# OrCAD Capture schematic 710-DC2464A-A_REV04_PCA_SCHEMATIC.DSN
size C; note: HOT SWAPPABLE SUPER CAPACITOR CHARGER AND BACKUP CONTROLLER
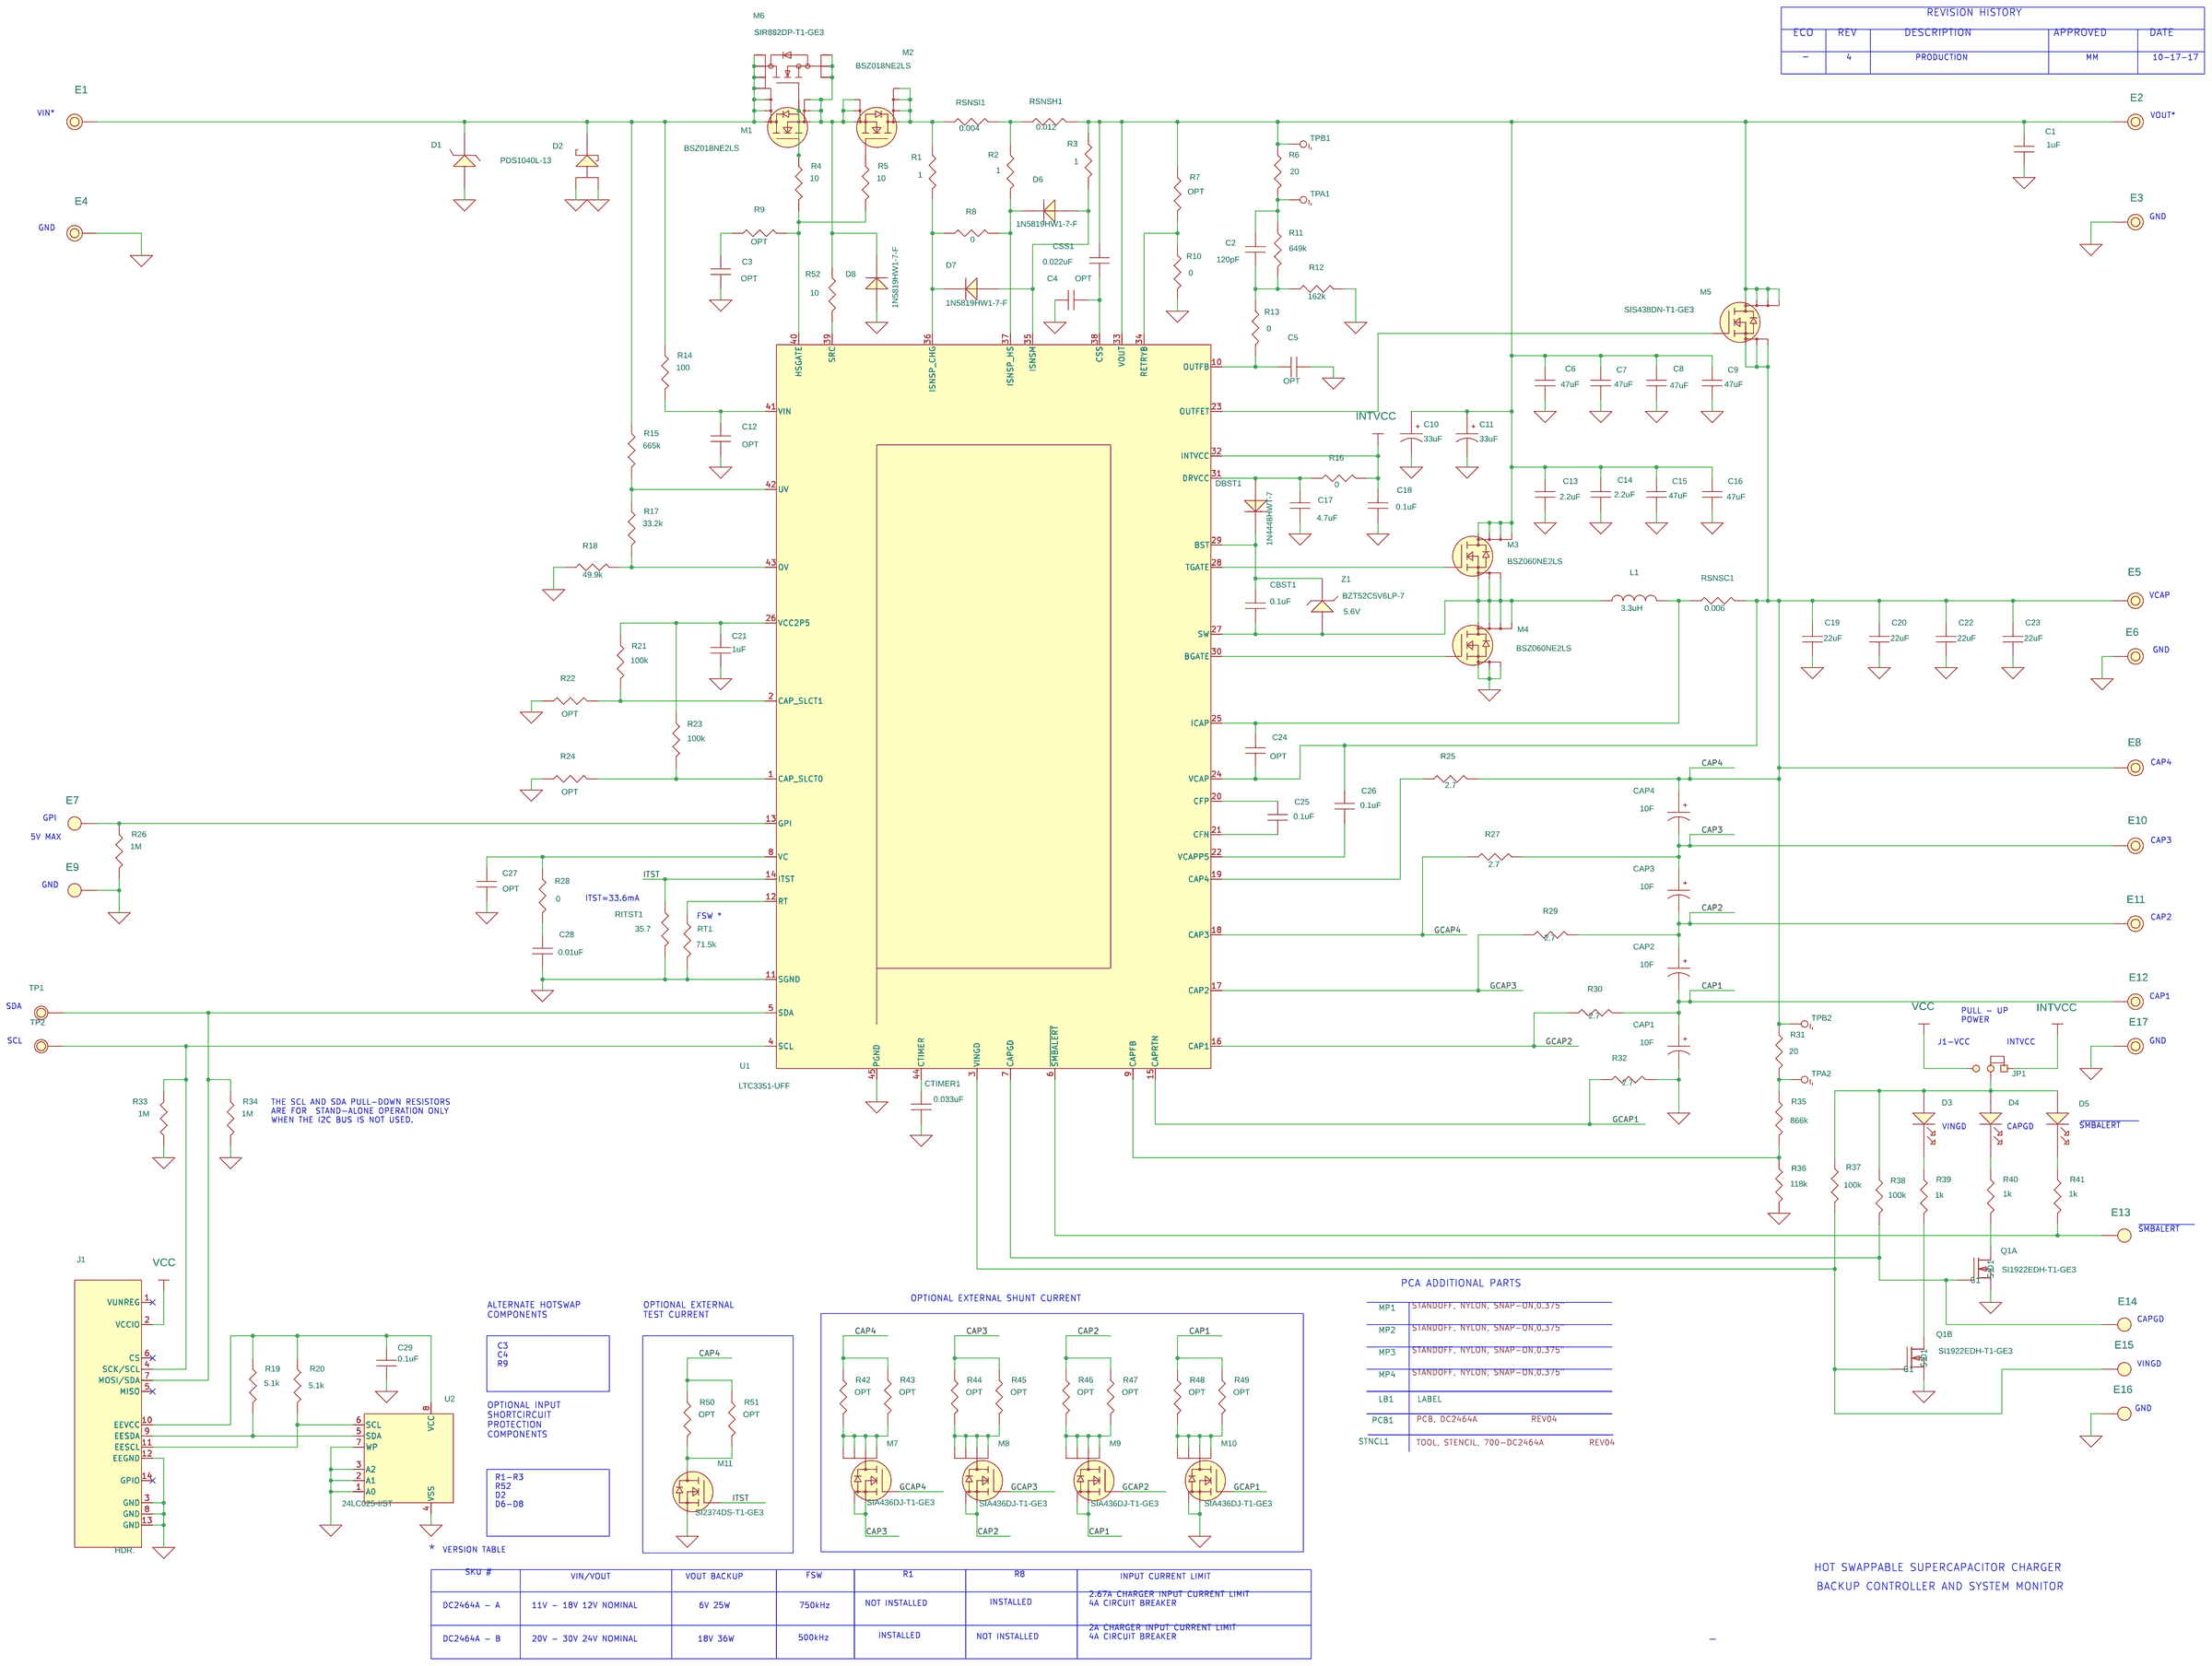
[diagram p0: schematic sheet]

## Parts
C1  1uF  [CC0603M]
C2  120pF  [CC0402M]
C3  OPT  [CC0603M]
C4  OPT  [CC0603M]
C5  OPT  [CC0402M]
C6  47uF  [CC1206M]
C7  47uF  [CC1206M]
C8  47uF  [CC1206M]
C9  47uF  [CC1206M]
C10  33uF  [PCAP_EEHZ_D8-M]
C11  33uF  [PCAP_EEHZ_D8-M]
C12  OPT  [CC0402M]
C13  2.2uF  [CC0402M]
C14  2.2uF  [CC0402M]
C15  47uF  [CC1206M]
C16  47uF  [CC1206M]
C17  4.7uF  [CC0603M]
C18  0.1uF  [CC0402M]
C19  22uF  [CC0805M]
C20  22uF  [CC0805M]
C21  1uF  [CC0402M]
C22  22uF  [CC0805M]
C23  22uF  [CC0805M]
C24  OPT  [CC0402M]
C25  0.1uF  [CC0402M]
C26  0.1uF  [CC0402M]
C27  OPT  [CC0402M]
C28  0.01uF  [CC0402M]
C29  0.1uF  [CC0402M]
CAP1  10F  [CAP-ESHSR-0010-0050C0-002R7]
CAP2  10F  [CAP-ESHSR-0010-0050C0-002R7]
CAP3  10F  [CAP-ESHSR-0010-0050C0-002R7]
CAP4  10F  [CAP-ESHSR-0010-0050C0-002R7]
CBST1  0.1uF  [CC0402M]
CSS1  0.022uF  [CC0603M]
CTIMER1  0.033uF  [CC0402M]
D1  SMBJ18A  [FAIRCHILD-DO-214AA]
D2  PDS1040L-13  [POWERDI5]
D3  GREEN  [LUMEX-SML-LX0603GW-TR]
D4  GREEN  [LUMEX-SML-LX0603GW-TR]
D5  SUPER RED  [LUMEX-SML-LX0603SRW-TR]
D6  1N5819HW1-7-F  [SOD-123F-N]
D7  1N5819HW1-7-F  [SOD-123F-N]
D8  1N5819HW1-7-F  [SOD-123F-N]
DBST1  1N4448HWT-7  [SOD-523N]
E1  TEST POINT  [MILLMAX2501]
E2  TEST POINT  [MILLMAX2501]
E3  TEST POINT  [MILLMAX2501]
E4  TEST POINT  [MILLMAX2501]
E5  TEST POINT  [MILLMAX2501]
E6  TEST POINT  [MILLMAX2501]
E7  TEST POINT  [MILLMAX2308]
E8  TEST POINT  [MILLMAX2501]
E9  TEST POINT  [MILLMAX2308]
E10  TEST POINT  [MILLMAX2501]
E11  TEST POINT  [MILLMAX2501]
E12  TEST POINT  [MILLMAX2501]
E13  TEST POINT  [MILLMAX2308]
E14  TEST POINT  [MILLMAX2308]
E15  TEST POINT  [MILLMAX2308]
E16  TEST POINT  [MILLMAX2308]
E17  TEST POINT  [MILLMAX2501]
J1  HDR.  [HD2X7-079-MOLEX]
JP1  HDR  [HD1X3-079]
L1  3.3uH  [IND-XAL7030]
LB1  LABEL  [895-0154_REV01]
M1  BSZ018NE2LS  [PG-TSDSON-8]
M2  BSZ018NE2LS  [PG-TSDSON-8]
M3  BSZ060NE2LS  [PG-TSDSON-8]
M4  BSZ060NE2LS  [PG-TSDSON-8]
M5  SIS438DN-T1-GE3  [POWERPAK1212-8S]
M6  SIR882DP-T1-GE3  [POWERPAKSO-8]
M7  SIA436DJ-T1-GE3  [POWERPAK-SC-70-6L-SINGLE]
M8  SIA436DJ-T1-GE3  [POWERPAK-SC-70-6L-SINGLE]
M9  SIA436DJ-T1-GE3  [POWERPAK-SC-70-6L-SINGLE]
M10  SIA436DJ-T1-GE3  [POWERPAK-SC-70-6L-SINGLE]
M11  SI2374DS-T1-GE3  [SOT23-3N]
MP1  STANDOFF, NYLON, SNAP-ON  [KEYSTONE_8829-8834]
MP2  STANDOFF, NYLON, SNAP-ON  [KEYSTONE_8829-8834]
MP3  STANDOFF, NYLON, SNAP-ON  [KEYSTONE_8829-8834]
MP4  STANDOFF, NYLON, SNAP-ON  [KEYSTONE_8829-8834]
PCB1  PCB, DC2464A
Q1  SI1922EDH-T1-GE3  [SC-70-6N-VISHAY]  (sections A,B)
R1  1  [CR0402M]
R2  1  [CR0402M]
R3  1  [CR0402M]
R4  10  [CR0402M]
R5  10  [CR0402M]
R6  20  [CR0402M]
R7  OPT  [CR0402M]
R8  0  [CR0402M]
R9  OPT  [CR0402M]
R10  0  [CR0402M]
R11  649k  [CR0402M]
R12  162k  [CR0402M]
R13  0  [CR0402M]
R14  100  [CR0402M]
R15  665k  [CR0402M]
R16  0  [CR0402M]
R17  33.2k  [CR0402M]
R18  49.9k  [CR0402M]
R19  5.1k  [CR0402M]
R20  5.1k  [CR0402M]
R21  100k  [CR0402M]
R22  OPT  [CR0402M]
R23  100k  [CR0402M]
R24  OPT  [CR0402M]
R25  2.7  [CR0805M]
R26  1M  [CR0402M]
R27  2.7  [CR0805M]
R28  0  [CR0402M]
R29  2.7  [CR0805M]
R30  2.7  [CR0805M]
R31  20  [CR0402M]
R32  2.7  [CR0805M]
R33  1M  [CR0402M]
R34  1M  [CR0402M]
R35  866k  [CR0402M]
R36  118k  [CR0402M]
R37  100k  [CR0402M]
R38  100k  [CR0402M]
R39  1k  [CR0402M]
R40  1k  [CR0402M]
R41  1k  [CR0402M]
R42  OPT  [CR2512N]
R43  OPT  [CR2512N]
R44  OPT  [CR2512N]
R45  OPT  [CR2512N]
R46  OPT  [CR2512N]
R47  OPT  [CR2512N]
R48  OPT  [CR2512N]
R49  OPT  [CR2512N]
R50  OPT  [CR2512N]
R51  OPT  [CR2512N]
R52  10  [CR0402M]
RITST1  35.7  [CR0402M]
RSNSC1  0.006  [1206-PRL1632]
RSNSH1  0.012  [1206-PRL1632]
RSNSI1  0.004  [1206-PRL1632]
RT1  71.5k  [CR0402M]
STNCL1  TOOL, STENCIL, 700-DC2464A
TP1  TEST PAD  [PADSTYLE2]
TP2  TEST PAD  [PADSTYLE2]
TPA1  COPPER FEATURE PAD  [PADSTYLE1]
TPA2  COPPER FEATURE PAD  [PADSTYLE1]
TPB1  COPPER FEATURE PAD  [PADSTYLE1]
TPB2  COPPER FEATURE PAD  [PADSTYLE1]
U1  LTC3351-UFF  [LTC-UFF-44-1762]
U2  24LC025-I/ST  [MICROCHIP-TSSOP-8]
XJP1  SHUNT
Z1  BZT52C5V6LP-7  [X1-DFN1006-2]

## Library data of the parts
C1 = CAP: CAP.,1uF,X5R,50V,10%,0603,AEC-Q200; CLASS: DISCRETE; Dielectric Type: X5R; FPLIST: CC0603N,CC0603L,CC0603M; Manufacturer: TDK; Manufacturer PN: CGA3E3X5R1H105K080AB; PART_NUMBER: 150-2446; Package Size: 0603; Package Type: SMD; Rated Voltage: 50V; Tolerance: 10%; UserField01: AEC-Q200
C2 = CAP: CAP.,120pF,C0G,50V,5%,0402; CLASS: DISCRETE; Dielectric Type: C0G; Manufacturer: Murata; Manufacturer PN: GRM1555C1H121JA01D; PART_NUMBER: 150-2443; Package Size: 0402; Rated Voltage: 50V; Temperature Coefficient: C0G; Tolerance: 5%
C3 C4 = CAP: CAP., OPTION, 0603; CLASS: DISCRETE; FPLIST: CC0603N,CC0603L,CC0603M; PART_NUMBER: 150-3038; Package Size: 0603; Package Type: SMD; UserField01: OPTION
C5 C12 C24 C27 = CAP: CAP., OPTION, 0402; CLASS: DISCRETE; FPLIST: CC0402N,CC0402L,CC0402M; PART_NUMBER: 150-3148; Package Size: 0402; Package Type: SMD
C6-C9 C15 C16 = CAP: CAP.,47uF,X5R,25V,20%,1206; CLASS: DISCRETE; Dielectric Type: X5R; FPLIST: CC1206N,CC1206L,CC1206M; Manufacturer: TDK; Manufacturer PN: C3216X5R1E476M160AC; PART_NUMBER: 150-0270; Package Size: 1206; Rated Voltage: 25V; Tolerance: 20%
C10 C11 = CAP_P_ALT: CAP.,33uF,ALUM.,50V,20%,SMD 6.3mmX7.7mm,AEC-Q200; CLASS: DISCRETE; Dielectric Type: ALUM.; FPLIST: PANASONIC_ZA_6.3X7.7,PCAP_EEHZ_D8-M; Manufacturer: PANASONIC; Manufacturer PN: EEHZA1H330XP; PART_NUMBER: 150-0335; Package Size: SMD 6.3mmX7.7mm; Rated Voltage: 50V; Tolerance: 20%; UserField01: AEC-Q200
C13 C14 = CAP: CAP.,2.2uF,X5R,25V,10%,0402; CLASS: DISCRETE; Dielectric Type: X5R; FPLIST: CC0402N,CC0402L,CC0402M; Manufacturer: TDK; Manufacturer PN: C1005X5R1E225K050BC; PART_NUMBER: 150-0271; Package Size: 0402; Rated Voltage: 25V; Tolerance: 10%
C17 = CAP: CAP.,4.7uF,X5R,16V,10%,0603; CLASS: DISCRETE; Dielectric Type: X5R; Manufacturer: AVX; Manufacturer PN: 0603YD475KAT2A; PART_NUMBER: 150-3182; Package Size: 0603; Rated Voltage: 16V; Tolerance: 10%
C18 C25 C26 C29 CBST1 = CAP: CAP.,0.1uF,X7R,16V,10%,0402; CLASS: DISCRETE; Dielectric Type: X7R; FPLIST: CC0402N,CC0402L,CC0402M; Manufacturer: AVX; Manufacturer PN: 0402YC104KAT2A; PART_NUMBER: 150-3065; Package Size: 0402; Package Type: SMD; Rated Voltage: 16V; Tolerance: 10%
C19 C20 C22 C23 = CAP: CAP.,22uF,X5R,16V,20%,0805; CLASS: DISCRETE; Dielectric Type: X5R; FPLIST: CC0805N,CC0805L,CC0805M; Manufacturer: TDK; Manufacturer PN: C2012X5R1C226M125AC; PART_NUMBER: 150-2100; Package Size: 0805; Package Type: Surface Mount; Rated Voltage: 16V; Tolerance: 20%
C21 = CAP: CAP.,1uF,X5R,16V,10%,0402; CLASS: DISCRETE; Dielectric Type: X5R; FPLIST: CC0402N,CC0402L,CC0402M; Manufacturer: TAIYO YUDEN; Manufacturer PN: EMK105BJ105KV-F; PART_NUMBER: 150-0250; Package Size: 0402; Rated Voltage: 16V; Tolerance: 10%
C28 = CAP: CAP.,0.01uF,X7R,16V,10%,0402; CLASS: DISCRETE; Dielectric Type: X7R; FPLIST: CC0402N,CC0402L,CC0402M; Manufacturer: AVX; Manufacturer PN: 0402YC103KAT2A; PART_NUMBER: 150-0146; Package Size: 0402; Rated Voltage: 16V; Tolerance: 10%
CAP1-CAP4 = CAP_P_ALT: CAP.,10F,ULTRA,2.7V,-10/+20%,THT,RADIAL; CLASS: DISCRETE; Dielectric Type: ULTRA; Manufacturer: NESSCAP CO. LTD.; Manufacturer PN: ESHSR-0010C0-002R7; PART_NUMBER: 150-0245; Package Size: THT; Rated Voltage: 2.7V; Tolerance: -10/+20%; UserField01: RADIAL
CSS1 = CAP: CAP.,0.022uF,X7R,100V,10%,0603; CLASS: DISCRETE; Dielectric Type: X7R; FPLIST: CC0603N,CC0603L,CC0603M; Manufacturer: TDK; Manufacturer PN: C1608X7R2A223K080AA; PART_NUMBER: 150-2444; Package Size: 0603; Package Type: Surface Mount, MLCC; Rated Voltage: 100V; Temperature Coefficient: X7R; Tolerance: 10%
CTIMER1 = CAP: CAP.,0.033uF,X5R,16V,10%,0402,AEC-Q200; CLASS: DISCRETE; Dielectric Type: X5R; Manufacturer: TDK; Manufacturer PN: CGA2B2X5R1C333K050BA; PART_NUMBER: 150-2445; Package Size: 0402; Package Type: Surface Mount, MLCC; Rated Voltage: 16V; Temperature Coefficient: X5R; Tolerance: 10%; UserField01: AEC-Q200
D1 = DIODE_TVS_B_ALT: DIODE,TVS,18V,600W,SMB; CLASS: DISCRETE; FPLIST: FAIRCHILD-DO-214AA,DO-214AA; Manufacturer: DIODES INC.; Manufacturer PN: SMBJ18A-13-F; PART_NUMBER: 210-0265; Package Size: SMB; Package Type: SMB; Rated Voltage: 18V
D2 = DIODE_SCHOTTKY_POWERDI5: DIODE,SCHOTTKY,40V,10A,PowerDI5; CLASS: DISCRETE; Manufacturer: DIODES INC.; PART_NUMBER: 210-0144; Package Type: PowerDI5; Rated Voltage: 40V
D3 D4 = LED_ALT: LED,GREEN,MILKY WHITE DIFF.,0603 SMD,565nm; CLASS: DISCRETE; Manufacturer: LUMEX; Manufacturer PN: SML-LX0603GW-TR; PART_NUMBER: 270-0095; Package Size: 0603 (1608 Metric); Package Type: 0603 SMD
D5 = LED_ALT: LED,SUPER RED,MILKY WHITE DIFF.,0603 SMD,660nm; CLASS: DISCRETE; Manufacturer: LUMEX; Manufacturer PN: SML-LX0603SRW-TR; PART_NUMBER: 270-0084; Package Size: 0603 (1608 Metric); Package Type: 0603 SMD
D6-D8 = DIODE_A_ALT: DIODE,SBR,40V,1A,SOD123F; CLASS: DISCRETE; FPLIST: SOD-123F-N,SOD-123F-L,SOD-123F-M; Manufacturer: DIODES INC.; PART_NUMBER: 210-0267; Package Size: SOD-123F; Package Type: SOD123F; Rated Voltage: 40V
DBST1 = DIODE_A_ALT: DIODE,GP SWITCHING,80V,125mA,SOD523,AEC-Q10X; CLASS: DISCRETE; Manufacturer: DIODES INC.; PART_NUMBER: 210-0128; Package Size: SC-79, SOD-523; Package Type: SOD523; Rated Voltage: 80V
E1-E6 E8 E10-E12 E17 = TESTPOINT_.219_MILL-MAX_2501: TEST POINT,TURRET,0.094",MTG. HOLE; CLASS: IO; Manufacturer: MILL-MAX; Manufacturer PN: 2501-2-00-80-00-00-07-0; PART_NUMBER: 260-0003
E7 E9 E13-E16 = TEST_POINT_.156_MILL-MAX_2308: TEST POINT,TURRET,0.064",MTG. HOLE; CLASS: IO; Manufacturer PN: 2308-2-00-80-00-00-07-0; PART_NUMBER: 260-0004
J1 = CONN_2X7_.079_MOLEX_RIBBON_A: CONN.,HDR.,MALE,2x7,2mm,THT, VERT,SHROUDED; CLASS: IO; Manufacturer: MOLEX; Manufacturer PN: 87831-1420; PART_NUMBER: 250-0403
JP1 = 3_PIN_HEADER_.079_SINGLE_ROW_D: CONN.,HDR,MALE,1x3,2mm,THT, STR; CLASS: IO; Manufacturer: Wurth Elektronik; Manufacturer PN: 62000311121; PART_NUMBER: 250-0484
L1 = IND_ALT: IND.,3.3uH,PWR.,20%,10A,21.45mOHMS,SMD 7.5mmX7.5mm,AEC-Q200; CLASS: DISCRETE; Manufacturer: COILCRAFT; Manufacturer PN: XAL7030-332MEB; PART_NUMBER: 200-0204; Package Size: SMD 7.5mmX7.5mm; Tolerance: 20%
LB1 = BLANK_LABEL: LABEL SPEC, DEMO BOARD SERIAL NUMBER; Manufacturer: BRADY; Manufacturer PN: THT-96-717-10; PART_NUMBER: 895-0154
M1 M2 = MOSFET_N-CH_G: XSTR.,MOSFET, N-CH,25V,23A,TSDSON-8; CLASS: DISCRETE; Manufacturer: INFINEON; Manufacturer PN: BSZ018NE2LSATMA1; PART_NUMBER: 240-0279; Package Size: 8-PowerTDFN; Package Type: TSDSON-8; Polarity: MOSFET N-Channel, Metal Oxide; Rated Power: 2.1W; Rated Voltage: 25V
M3 M4 = MOSFET_N-CH_G: XSTR.,MOSFET, N-CH,25V,12A,TSDSON-8; CLASS: DISCRETE; Manufacturer: INFINEON; Manufacturer PN: BSZ060NE2LSATMA1; PART_NUMBER: 240-0121; Package Size: 8-PowerTDFN; Package Type: TSDSON-8; Polarity: MOSFET N-Channel, Metal Oxide; Rated Power: 2.1W; Rated Voltage: 25V
M5 = SIS438DN-T1-GE3: XSTR.,MOSFET, N-CH,20V,16A,PowerPAK 1212-8; CLASS: DISCRETE; Manufacturer: VISHAY; Manufacturer PN: SiS438DN-T1-GE3; PART_NUMBER: 240-0120; Package Size: PowerPAK-1212-8; Package Type: PowerPAK 1212-8; Polarity: N-Channel; Rated Voltage: 20V
M6 = SIR882DP-T1-GE3: XSTR.,MOSFET, N-CH,100V,60A,PPAK SO-8; CLASS: DISCRETE; FPLIST: VISHAY_PPAK_SO-8,POWERPAKSO-8; Manufacturer: VISHAY; PART_NUMBER: 240-0026; Package Size: PowerPAK® SO-8; Package Type: PPAK SO-8; Polarity: MOSFET N-Channel, Metal Oxide; Rated Power: 83W; Rated Voltage: 100V
M7-M10 = SIA436DJ-T1-GE3: MOSFET, N-CH 8V 12A, SC70-6L; CLASS: DISCRETE; Manufacturer: Vishay Siliconix; PART_NUMBER: TMP-1089; Package Size: PowerPAK® SC-70-6; Package Type: Surface Mount; Polarity: MOSFET N-Channel, Metal Oxide; Rated Power: 19W
M11 = SI2374DS-T1-GE3: MOSFET, N-CH 20V 5.9A 1.7W, SOT-23; CLASS: DISCRETE; Manufacturer: Vishay Semiconductors; PART_NUMBER: TMP-1088
MP1-MP4 = BLANK_PINLESS_MECHANICAL_PART: STANDOFF, NYLON, SNAP-ON,0.375"; CLASS: DISCRETE; Manufacturer: KEYSTONE; Manufacturer PN: 8832; PART_NUMBER: 763-0008
PCB1 = BLANK_PCB_PART: BOM Notes: REV04; CLASS: PCB; Manufacturer: PHASE 3 TECHNOLOGIES INC.; Manufacturer PN: 600-DC2464A; PART_NUMBER: 600-DC2464A
Q1 = SI1922EDH-T1-GE3: XSTR.,MOSFET, DUAL N-CH,20V,1.3A,SOT-363; CLASS: DISCRETE; Manufacturer: VISHAY; Manufacturer PN: Si1922EDH-T1-GE3; PART_NUMBER: 240-0036; Package Size: 6-TSSOP, SC-88, SOT-363; Package Type: SOT-363; Polarity: 2 N-Channel (Dual); Rated Power: 1.25W; Rated Voltage: 20V
R1-R3 = RES: RES.,1 OHM,1%,1/16W,0402; CLASS: DISCRETE; FPLIST: CR0402N,CR0402L,CR0402M; Manufacturer: VISHAY; Manufacturer PN: CRCW04021R00FKED; PART_NUMBER: 100-0241; Package Size: 0402; Rated Power: 1/16W; Temperature Coefficient: 100ppm; Tolerance: 1%
R4 R5 R52 = RES: RES.,10 OHMS,5%,1/16W,0402; CLASS: DISCRETE; FPLIST: CR0402N,CR0402L,CR0402M; Manufacturer: VISHAY; Manufacturer PN: CRCW040210R0JNED; PART_NUMBER: 100-2889; Package Size: 0402; Rated Power: 1/16W; Temperature Coefficient: 200ppm; Tolerance: 5%
R6 R31 = RES: RES.,20 OHMS,1%,1/16W,0402; CLASS: DISCRETE; FPLIST: CR0402N,CR0402L,CR0402M; Manufacturer: NIC; Manufacturer PN: NRC04F20R0TRF; PART_NUMBER: 100-0250; Package Size: 0402; Rated Power: 1/16W; Temperature Coefficient: 100ppm; Tolerance: 1%
R7 R9 R22 R24 = RES: RES., OPTION, 0402; CLASS: DISCRETE; FPLIST: CR0402N,CR0402L,CR0402M; PART_NUMBER: 100-0357; Package Size: 0402
R8 R10 R13 R16 R28 = RES: RES.,0 OHM,1/16W,0402; CLASS: DISCRETE; FPLIST: CR0402N,CR0402L,CR0402M; Manufacturer: ROHM; Manufacturer PN: MCR01MZPJ000; PART_NUMBER: 100-0025; Package Size: 0402; Rated Power: 1/16W
R11 = RES: RES.,649k OHMS,1%,1/16W,0402; CLASS: DISCRETE; FPLIST: CR0402N,CR0402L,CR0402M; Manufacturer: NIC; Manufacturer PN: NRC04F6493TRF; PART_NUMBER: 100-0251; Package Size: 0402; Rated Power: 1/16W; Temperature Coefficient: 100ppm/C; Tolerance: 1%
R12 = RES: RES.,162k OHMS,1%,1/16W,0402; CLASS: DISCRETE; FPLIST: CR0402N,CR0402L,CR0402M; Manufacturer: VISHAY; Manufacturer PN: CRCW0402162KFKED; PART_NUMBER: 100-0252; Package Size: 0402; Rated Power: 1/16W; Temperature Coefficient: 100ppm/C; Tolerance: 1%
R14 = RES: RES.,100 OHMS,1%,1/16W,0402; CLASS: DISCRETE; FPLIST: CR0402N,CR0402L,CR0402M; Manufacturer: NIC; Manufacturer PN: NRC04F1000TRF; PART_NUMBER: 100-2626; Package Size: 0402; Rated Power: 1/16W; Temperature Coefficient: 100ppm/C; Tolerance: 1%
R15 = RES: RES.,665k OHMS,1%,1/16W,0402; CLASS: DISCRETE; FPLIST: CR0402N,CR0402L,CR0402M; Manufacturer: NIC; Manufacturer PN: NRC04F6653TRF; PART_NUMBER: 100-0460; Package Size: 0402; Rated Power: 1/16W; Temperature Coefficient: 100ppm; Tolerance: 1%
R17 = RES: RES.,33.2k OHMS,1%,1/16W,0402; CLASS: DISCRETE; FPLIST: CR0402N,CR0402L,CR0402M; Manufacturer: VISHAY; Manufacturer PN: CRCW040233K2FKED; PART_NUMBER: 100-2946; Package Size: 0402; Rated Power: 1/16W; Temperature Coefficient: 100ppm; Tolerance: 1%
R18 = RES: RES.,AEC-Q200,49.9k OHMS,1%,1/16W,0402; CLASS: DISCRETE; FPLIST: CR0402N,CR0402L,CR0402M; Manufacturer: PANASONIC; Manufacturer PN: ERJ2RKF4992X; PART_NUMBER: 100-0097; Package Size: 0402; Rated Power: 1/16W; Temperature Coefficient: 100ppm/C; Tolerance: 1%
R19 R20 = RES: RES.,5.1k OHMS,5%,1/16W,0402; CLASS: DISCRETE; FPLIST: CR0402N,CR0402L,CR0402M; Manufacturer: NIC; Manufacturer PN: NRC04J512TRF; PART_NUMBER: 100-2399; Package Size: 0402; Rated Power: 1/16W; Temperature Coefficient: 200ppm/C; Tolerance: 5%
R21 R23 R37 R38 = RES: RES.,100k OHMS,5%,1/16W,0402; CLASS: DISCRETE; FPLIST: CR0402N,CR0402L,CR0402M; Manufacturer: YAGEO; Manufacturer PN: RC0402JR-07100KL; PART_NUMBER: 100-0058; Package Size: 0402; Rated Power: 1/16W; Temperature Coefficient: 100ppm/C; Tolerance: 5%
R25 R27 R29 R30 R32 = RES: RES.,ANTI-SURGE, AEC-Q200,2.7 OHMS,5%,1/2W,0805; CLASS: DISCRETE; FPLIST: CR0805N,CR0805L,CR0805M; Manufacturer: PANASONIC; Manufacturer PN: ERJ-P6WJ2R7V; PART_NUMBER: 100-0871; Package Size: 0805; Rated Power: 1/2W; Temperature Coefficient: -100ppm to +600ppm; Tolerance: 5%
R26 R33 R34 = RES: RES.,1M OHMS,5%,1/16W,0402; CLASS: DISCRETE; FPLIST: CR0402N,CR0402L,CR0402M; Manufacturer: YAGEO; Manufacturer PN: RC0402JR-071ML; PART_NUMBER: 100-0096; Package Size: 0402; Rated Power: 1/16W; Temperature Coefficient: 100ppm/C; Tolerance: 5%
R35 = RES: RES.,866k OHMS,1%,1/16W,0402; CLASS: DISCRETE; FPLIST: CR0402N,CR0402L,CR0402M; Manufacturer: NIC; Manufacturer PN: NRC04F8663TRF; PART_NUMBER: 100-0256; Package Size: 0402; Rated Power: 1/16W; Temperature Coefficient: 100ppm/C; Tolerance: 1%
R36 = RES: RES.,118k OHMS,1%,1/16W,0402; CLASS: DISCRETE; FPLIST: CR0402N,CR0402L,CR0402M; Manufacturer: NIC; Manufacturer PN: NRC04F1183TRF; PART_NUMBER: 100-0257; Package Size: 0402; Rated Power: 1/16W; Temperature Coefficient: 100ppm/C; Tolerance: 1%
R39-R41 = RES: RES.,1k OHMS,5%,1/16W,0402; CLASS: DISCRETE; FPLIST: CR0402N,CR0402L,CR0402M; Manufacturer: NIC; Manufacturer PN: NRC04J102TRF; PART_NUMBER: 100-2397; Package Size: 0402; Rated Power: 1/16W; Temperature Coefficient: 200ppm; Tolerance: 5%
R42-R51 = RES: RES., OPTION, 2512; CLASS: DISCRETE; PART_NUMBER: 100-2376; Package Size: 2512
RITST1 = RES: RES.,AEC-Q200,35.7 OHMS,1%,1/16W,0402; CLASS: DISCRETE; FPLIST: CR0402N,CR0402L,CR0402M; Manufacturer: VISHAY; Manufacturer PN: CRCW040235R7FKED; PART_NUMBER: 100-0872; Package Size: 0402; Rated Power: 1/16W; Temperature Coefficient: 100ppm; Tolerance: 1%
RSNSC1 = RES: RES.,SENSE,0.006 OHMS,1%,1W,1206 (0612); CLASS: DISCRETE; FPLIST: CR1206N,CR1206L,CR1206M,1206-PRL1632; Manufacturer: Susumu; Manufacturer PN: PRL1632-R006-F-T1; PART_NUMBER: 100-0258; Package Size: 1206 (0612); Rated Power: 1W; Tolerance: 1%
RSNSH1 = RES: RES.,SENSE,0.012 OHM,1%,1W,1206 (0612); CLASS: DISCRETE; Manufacturer: Susumu; Manufacturer PN: PRL1632-R012-F-T1; PART_NUMBER: 100-0873; Package Size: 1206 (0612); Rated Power: 1W; Tolerance: 1%
RSNSI1 = RES: RES.,SENSE,AEC-Q200,0.004 OHM,1%,1.5W,1206 (0612) LONG-SIDE TERM.; CLASS: DISCRETE; Manufacturer: Susumu; Manufacturer PN: KRL3216E-C-R004-F-T1; PART_NUMBER: 100-0874; Package Size: 1206 (0612) LONG-SIDE TERM.; Rated Power: 1.5W; Tolerance: 1%
RT1 = RES: RES.,71.5k OHMS,1%,1/16W,0402; CLASS: DISCRETE; FPLIST: CR0402N,CR0402L,CR0402M; Manufacturer: NIC; Manufacturer PN: NRC04F7152TRF; PART_NUMBER: 100-0255; Package Size: 0402; Rated Power: 1/16W; Temperature Coefficient: 100ppm/C; Tolerance: 1%
STNCL1 = BLANK_STENCIL_PART: BOM Notes: REV04; CLASS: DISCRETE; Manufacturer: LINEAR TECH.; Manufacturer PN: 830-DC2464A; PART_NUMBER: 830-DC2464A
TP1 TP2 = PAD_STYLE_A: TESTPOINT, PCB COPPER FEATURE; CLASS: IO; Manufacturer: N/A; Manufacturer PN: N/A; PART_NUMBER: PCBPADS-1
TPA1 TPA2 TPB1 TPB2 = PAD_SMALL_FILLED: TESTPOINT, PCB COPPER FEATURE; CLASS: IO; Manufacturer: N/A; Manufacturer PN: N/A; PART_NUMBER: PCBPADS-11
U1 = LTC3351-UFF: SCAP Charger and Backup Controller with Hot Swap,QFN-44(UFF); CLASS: IC; Manufacturer: LINEAR TECH.; Manufacturer PN: LTC3351EUFF#PBF; PART_NUMBER: LTC3351EUFF#PBF; Package Size: LTC-UFF-40; Package Type: QFN-44(UFF)
U2 = 24LC025-I_ST_TSSOP-8_B: IC, MEMORY,EEPROM,2Kb (256x8),TSSOP-8,400kHz; CLASS: IC; Manufacturer: Microchip; PART_NUMBER: 380-0087; Package Size: TSSOP-8; Package Type: TSSOP-8
XJP1 = SHUNT_2MM_B: CONN.,SHUNT,FEMALE,2 POS,2mm; CLASS: IO; Manufacturer: Wurth Elektronik; Manufacturer PN: 60800213421; PART_NUMBER: 250-0485
Z1 = ZENER_ALT: DIODE,ZENER,5.6V,250MW,DFN1006-2; BOM Notes: Z1 OPTIONAL; CLASS: DISCRETE; Manufacturer: DIODES INC.; PART_NUMBER: TMP-1682; Package Size: 2-UFDFN; Package Type: Surface Mount; Rated Voltage: 5.6V

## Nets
GND: C1.2 C3.2 C4.1 C5.2 C6.2 C7.2 C8.2 C9.2 C10.2 C11.2 C12.2 C13.2 C14.2 C15.2 C16.2 C17.2 C18.2 C19.2 C20.2 C21.2 C22.2 C23.2 C27.2 C28.2 C29.2 CAP1.2 CTIMER1.2 D1.2(A) D2.2 D2.3 D8.2(A) E3.1 E4.1 E6.1 E9.1(A) E16.1(A) E17.1 J1.3(GND) J1.8(GND) J1.12(EEGND) J1.13(GND) M4.1(S) M4.2(Stab) M4.3(Stab1) M10.4(S) M10.7(S) M11.2(S) Q1.1(S1) Q1.4(S1) R10.2 R12.2 R18.1 R22.1 R24.1 R26.2 R32.2 R33.2 R34.2 R36.2 RITST1.2 RT1.2 U1.11(SGND) U1.45(PGND) U2.1(A0) U2.2(A1) U2.3(A2) U2.4(VSS) U2.7(WP)
VCC: J1.2(VCCIO) JP1.3
CAP1: CAP1.1 CAP2.2 E12.1 M9.4(S) M9.7(S) R30.2 R48.1 R49.1
CAP2: CAP2.1 CAP3.2 E11.1 M8.4(S) M8.7(S) R29.2 R46.1 R47.1
CAP3: CAP3.1 CAP4.2 E10.1 M7.4(S) M7.7(S) R27.2 R44.1 R45.1
CAP4: C19.1 C20.1 C22.1 C23.1 C24.2 C26.1 CAP4.1 E5.1 E8.1 M5.1(S) M5.2(Stab) M5.3(Stab1) R25.2 R31.1 R42.1 R43.1 R50.1 R51.1 RSNSC1.2 TPB2.1 U1.24(VCAP)
GCAP1: M10.3(G) R32.1 U1.15(CAPRTN)
GCAP2: M9.3(G) R30.1 U1.16(CAP1)
GCAP3: M8.3(G) R29.1 U1.17(CAP2)
GCAP4: M7.3(G) R27.1 U1.18(CAP3)
INTVCC: C18.1 JP1.1 R16.2 U1.32(INTVCC)
ITST: M11.1(G) RITST1.1 U1.14(ITST)
N16741921: M11.3(D) R50.2 R51.2
N16741933: C1.1 C6.1 C7.1 C8.1 C9.1 C10.1 C11.1 C13.1 C14.1 C15.1 C16.1 CSS1.1 E2.1 M3.5(D) M3.6(Dtab) M3.7(Dtab1) M3.8(Dtab2) M5.5(D) M5.6(Dtab) M5.7(Dtab1) M5.8(Dtab2) R3.1 R6.1 R7.1 RSNSH1.2 TPB1.1 U1.33(VOUT)
N16741965: CBST1.1 DBST1.1(C) U1.29(BST) Z1.1(C)
N16742001: M7.1(D) M7.2(D) M7.5(D) M7.6(D) R42.2 R43.2
N16742141: C2.2 R11.2 R12.1 R13.1
N16742193: C29.1 J1.10(EEVCC) R19.1 R20.1 U2.8(VCC)
N16742255: R17.2 R18.2 U1.43(OV)
N16742281: M8.1(D) M8.2(D) M8.5(D) M8.6(D) R44.2 R45.2
N16742341: R21.2 R22.2 U1.2(CAP_SLCT1)
N16742345: M9.1(D) M9.2(D) M9.5(D) M9.6(D) R46.2 R47.2
N16742509: M10.1(D) M10.2(D) M10.5(D) M10.6(D) R48.2 R49.2
N16742663: C21.1 R21.1 R23.1 U1.26(VCC2P5)
N16742861: CBST1.2 L1.1 M3.1(S) M3.2(Stab) M3.3(Stab1) M4.5(D) M4.6(Dtab) M4.7(Dtab1) M4.8(Dtab2) U1.27(SW) Z1.2(A)
N16742881: M5.4(G) U1.23(OUTFET)
N16742943: R2.1 RSNSH1.1 RSNSI1.2
N16742981: C4.2 CSS1.2 U1.38(CSS)
N16743073: C2.1 R6.2 R11.1 TPA1.1
N16743265: D1.1(C) D2.1 E1.1 M1.5(D) M1.6(Dtab) M1.7(Dtab1) M1.8(Dtab2) M6.5(D) M6.6(D) M6.7(D) M6.8(D) R14.1 R15.1
N16743307: J1.7(MOSI/SDA) R34.1 TP1.1 U1.5(SDA)
N16743441: J1.4(SCK/SCL) R33.1 TP2.1 U1.4(SCL)
N16743587: C5.1 R13.2 U1.10(OUTFB)
N16743623: R4.2 R5.2 R9.2 U1.40(HSGATE)
N16743679: C24.1 L1.2 RSNSC1.1 U1.25(ICAP)
N16743723: C12.1 R14.2 U1.41(VIN)
N16743747: R15.2 R17.1 U1.42(UV)
N16743779: R23.2 R24.2 U1.1(CAP_SLCT0)
N16743821: D3.2(ANODE) D4.2(ANODE) D5.2(ANODE) JP1.2 R37.1 R38.1
N16744003: C27.1 R28.1 U1.8(VC)
N16744187: CTIMER1.1 U1.44(CTIMER)
N16744353: R25.1 U1.19(CAP4)
N16744401: D3.1(CATHODE) R39.1
N16744405: D4.1(CATHODE) R40.1
N16744409: D5.1(CATHODE) R41.1
N16744417: E13.1(A) R41.2 U1.6(~{SMBALERT})
N16744461: E7.1(A) R26.1 U1.13(GPI)
N16744573: C28.1 R28.2
N16744637: R31.2 R35.1 TPA2.1
N16744641: R35.2 R36.1 U1.9(CAPFB)
N16744867: C17.1 DBST1.2(A) R16.1 U1.31(DRVCC)
N16744937: M2.5(D) M2.6(Dtab) M2.7(Dtab1) M2.8(Dtab2) R1.1 RSNSI1.1
N16745099: C25.1 U1.20(CFP)
N16745299: Q1.6(D1) R40.2
N16745361: M3.4(G) U1.28(TGATE)
N16745545: E15.1(A) Q1.5(G1) R37.2 U1.3(VINGD)
N16745553: Q1.3(D1) R39.2
N16745623: E14.1(A) Q1.2(G1) R38.2 U1.7(CAPGD)
N16745823: RT1.1 U1.12(RT)
N16746053: C25.2 U1.21(CFN)
N16746077: C26.2 U1.22(VCAPP5)
N16746463: M4.4(G) U1.30(BGATE)
N16770121: J1.11(EESCL) R20.2 U2.6(SCL)
N16771035: J1.9(EESDA) R19.2 U2.5(SDA)
N16784247: D7.1(C) R1.2 R8.1 U1.36(ISNSP_CHG)
N16792325: M1.4(G) M6.4(G) R4.1
N16793615: R7.2 R10.1 U1.34(RETRYB)
N16804128: D8.1(C) M1.1(S) M1.2(Stab) M1.3(Stab1) M2.1(S) M2.2(Stab) M2.3(Stab1) M6.1(S) M6.2(S) M6.3(S) R52.1
N16980257: D6.2(A) D7.2(A) R3.2 U1.35(ISNSM)
N16994957: C3.1 R9.1
N17028941: D6.1(C) R2.2 R8.2 U1.37(ISNSP_HS)
N17314926: R52.2 U1.39(SRC)
N17322413: M2.4(G) R5.1

Not connected (* = marked no-connect by the designer): J1 1(VUNREG)* 5(MISO)* 6(CS)* 14(GPIO)*

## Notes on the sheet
- REVISION HISTORY
- ECO
- REV
- DESCRIPTION
- APPROVED
- DATE
- -
- 4
- PRODUCTION
- MM
- 10-17-17
- VIN*
- VOUT*
- GND
- GND
- VCAP
- GND
- CAP4
- GPI
- 5V MAX
- CAP3
- GND
- ITST=33.6mA
- FSW *
- CAP2
- SDA
- CAP1
- PULL - UP
  POWER
- SCL
- J1-VCC
- INTVCC
- GND
- THE SCL AND SDA PULL-DOWN RESISTORS
  ARE FOR  STAND-ALONE OPERATION ONLY
  WHEN THE I2C BUS IS NOT USED.
- VINGD
- CAPGD
- SMBALERT
- SMBALERT
- PCA ADDITIONAL PARTS
- ALTERNATE HOTSWAP
  COMPONENTS
- OPTIONAL EXTERNAL
  TEST CURRENT
- OPTIONAL EXTERNAL SHUNT CURRENT
- CAPGD
- C3
  C4
  R9
- VINGD
- OPTIONAL INPUT
  SHORTCIRCUIT
  PROTECTION
  COMPONENTS
- GND
- R1-R3
  R52
  D2
  D6-D8
- *
- VERSION TABLE
- SKU #
- HOT SWAPPABLE SUPERCAPACITOR CHARGER
- VIN/VOUT
- VOUT BACKUP
- FSW
- R1
- R8
- INPUT CURRENT LIMIT
- BACKUP CONTROLLER AND SYSTEM MONITOR
- 2.67A CHARGER INPUT CURRENT LIMIT
  4A CIRCUIT BREAKER
- DC2464A - A
- 11V - 18V 12V NOMINAL
- 6V 25W
- 750kHz
- NOT INSTALLED
- INSTALLED
- 500kHz
- INSTALLED
- NOT INSTALLED
- 2A CHARGER INPUT CURRENT LIMIT
  4A CIRCUIT BREAKER
- -
- DC2464A - B
- 20V - 30V 24V NOMINAL
- 18V 36W
